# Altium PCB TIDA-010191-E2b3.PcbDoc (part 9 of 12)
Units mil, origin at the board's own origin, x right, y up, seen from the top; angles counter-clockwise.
Board outline 9842.52 x 9842.4 mil, 6 copper layers (Layer 1 - Top Layer, Layer 2 - GND Layer, Layer 3 - Signal, Layer 4 - Signal, Layer 5 - GND, Bottom Layer), stack 59.9 mil thick; 1178 components, 642 nets, 3329 pads, 2967 vias.
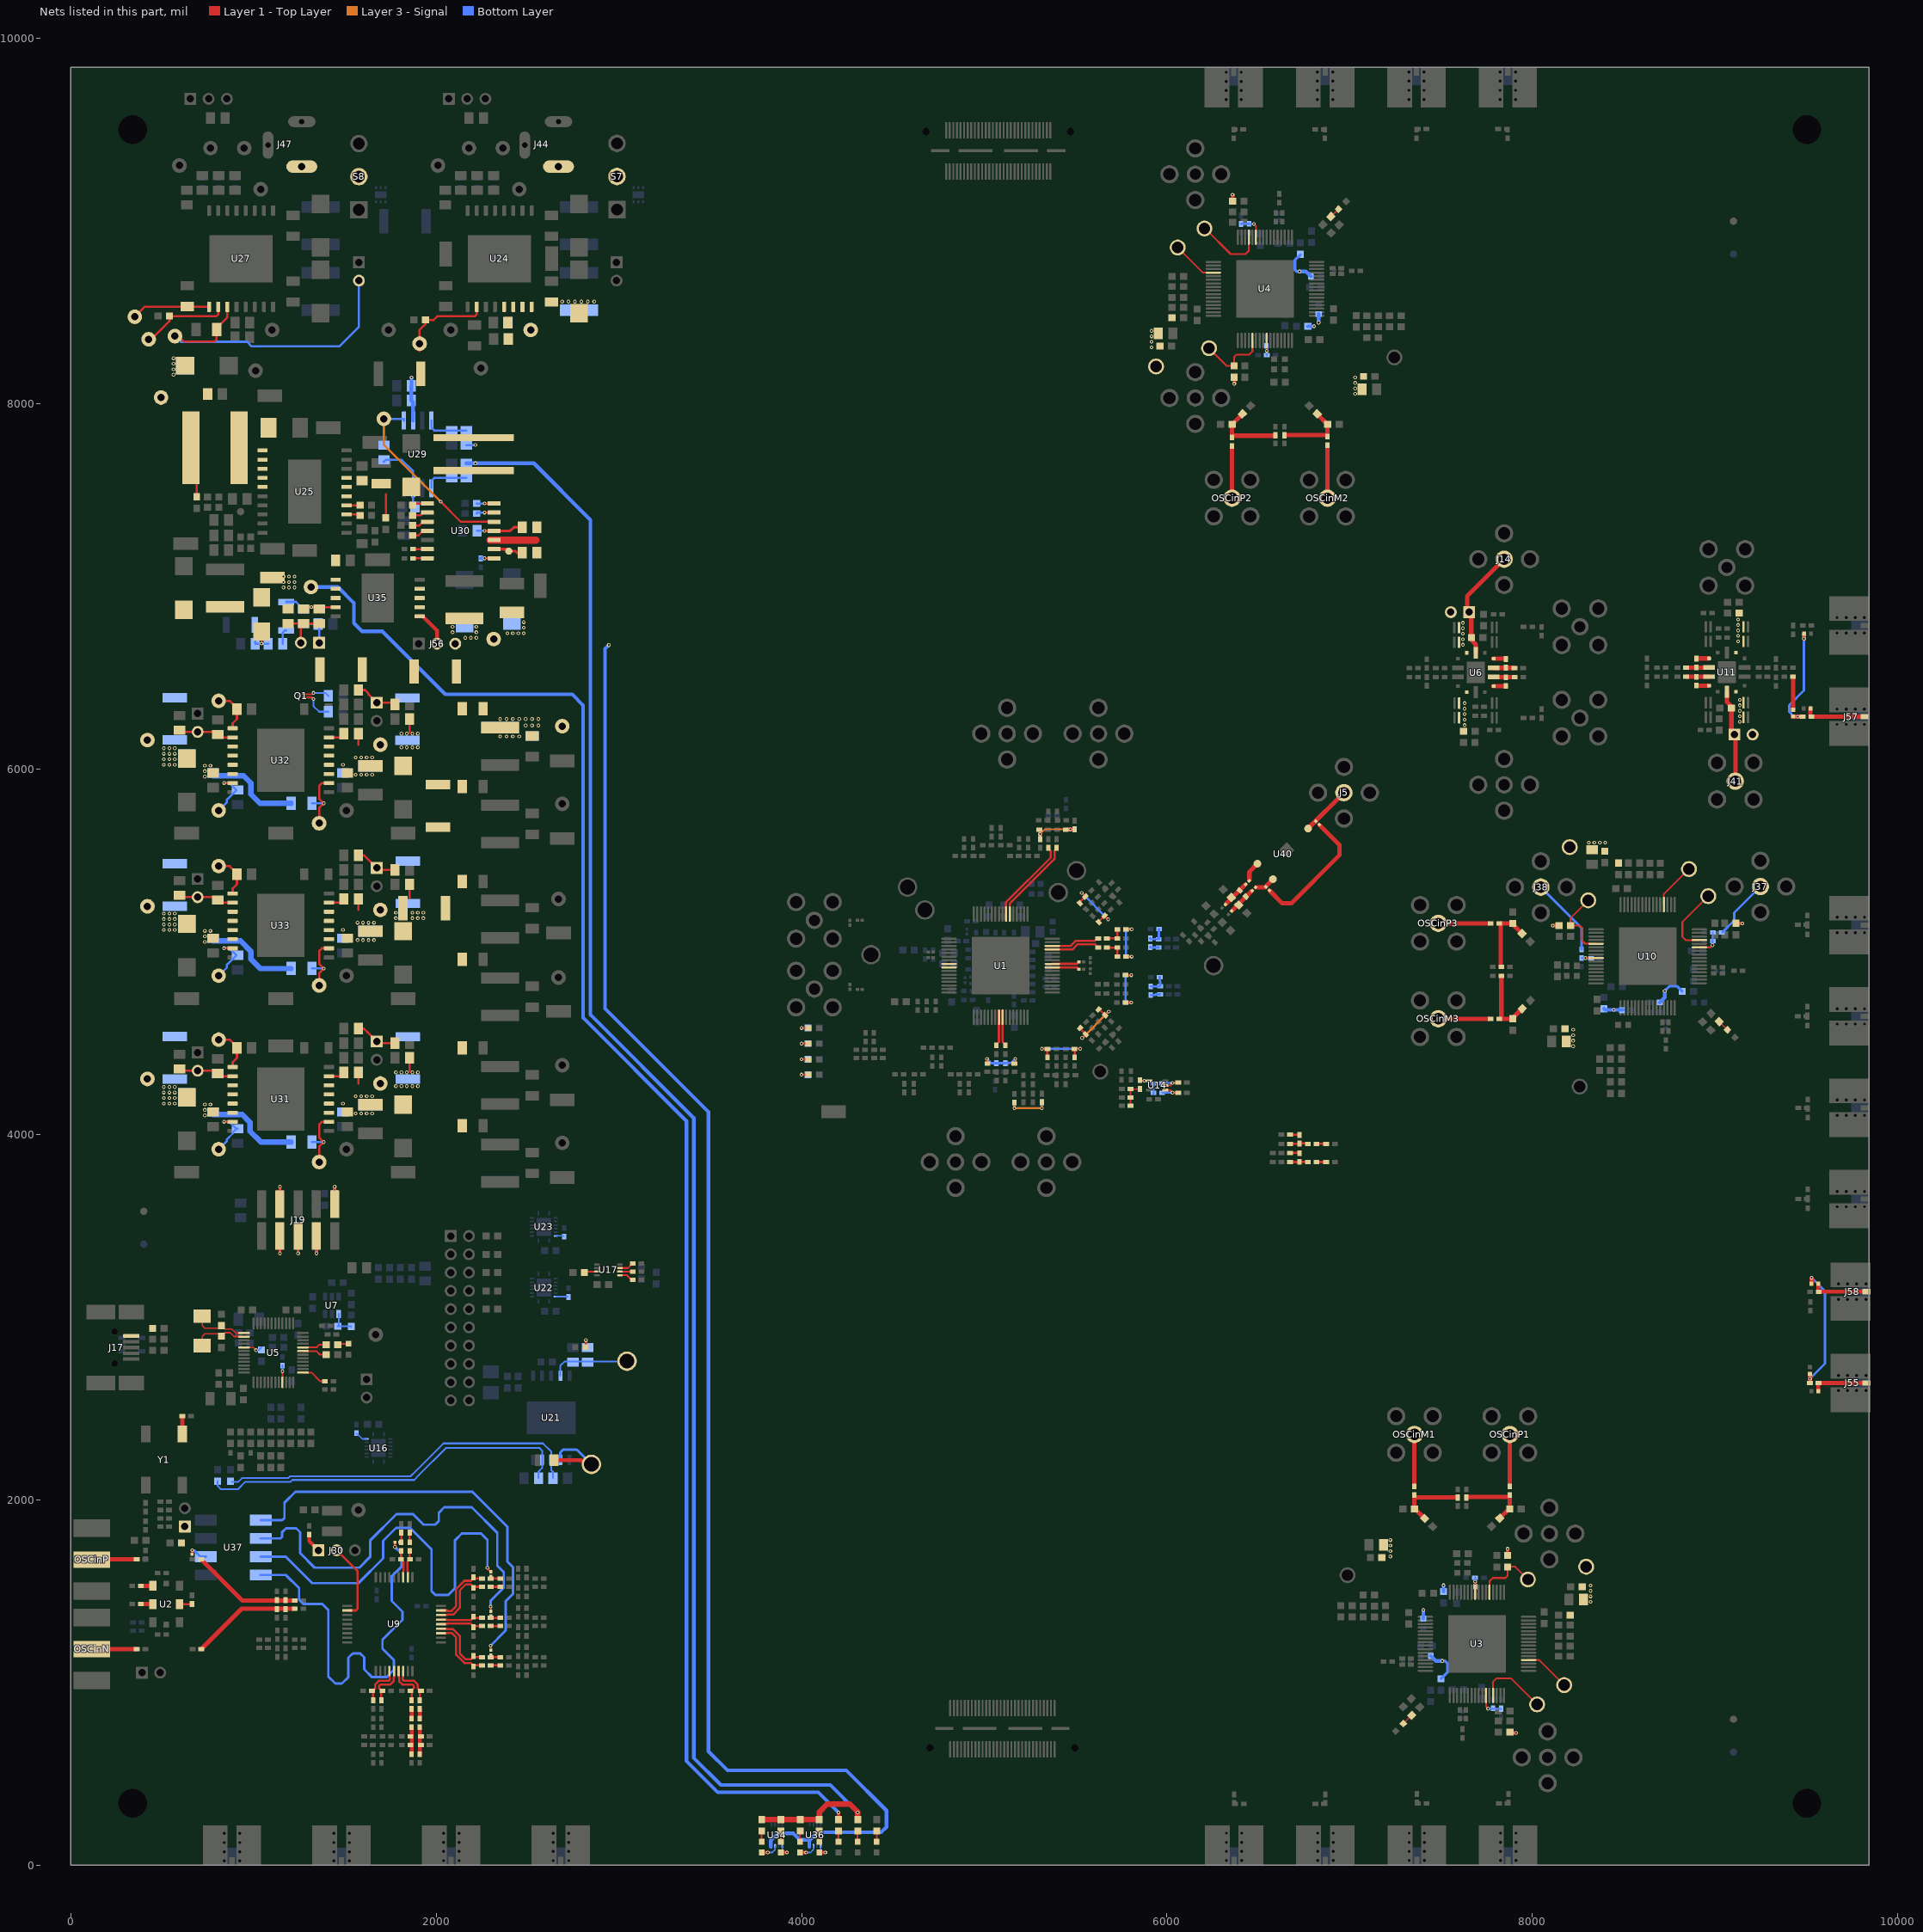
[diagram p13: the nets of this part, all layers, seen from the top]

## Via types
v1: diameter 20, hole 10, Layer 1 - Top Layer to Bottom Layer, tented both sides, 2595 vias
v2: diameter 19.68, hole 7.87, Layer 1 - Top Layer to Bottom Layer, 308 vias
v3: diameter 19.68, hole 7.87, Layer 1 - Top Layer to Bottom Layer, tented both sides, 25 vias
v4: diameter 20, hole 10, Layer 1 - Top Layer to Bottom Layer, 21 vias
v5: diameter 41, hole 25, Layer 1 - Top Layer to Bottom Layer, 10 vias
v6: diameter 24, hole 12, Layer 1 - Top Layer to Bottom Layer, tented both sides, 4 vias
v7: diameter 24, hole 8, Layer 1 - Top Layer to Bottom Layer, tented both sides, 1 vias
v8: diameter 24/24/24/24/24/24 (per signal layer), hole 8, Layer 1 - Top Layer to Bottom Layer, tented both sides, 1 vias
v9: diameter 30, hole 12, Layer 1 - Top Layer to Bottom Layer, tented both sides, 1 vias
v10: diameter 20/20/20/20/20/20 (per signal layer), hole 10, Layer 1 - Top Layer to Bottom Layer, tented both sides, 1 vias

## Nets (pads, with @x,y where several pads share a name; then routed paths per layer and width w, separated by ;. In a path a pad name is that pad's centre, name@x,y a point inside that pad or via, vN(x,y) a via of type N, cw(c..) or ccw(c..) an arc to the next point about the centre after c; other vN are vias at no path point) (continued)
NetC262_2: C262.2 J46.2 TP33.1 U27.11 | length 1736.6
  Layer 1 - Top Layer w12: TP33.1@562.99,8365.23 595.17,8365.23 620.08,8340.32 784.32,8340.32 799.02,8355.02 799.02,8405.93 C262.2@800.09,8407 800.09,8417.83 819.68,8437.42 820.57,8437.42 857.56,8474.41 U27.11@857.56,8531.5
  Bottom Layer w12: 602,8340 966,8340 991,8315 1470,8315 1577.56,8422.56 J46.2@1577.56,8675
NetC263_2: C263.2 TP31.1 U27.9 | length 430.3
  Layer 1 - Top Layer w12: TP31.1@351,8477 406.91,8532.91 C263.2@637.56,8532.91 638.97,8531.5 U27.9@757.56,8531.5
NetC264_1: C264.1 R485.1 U29.3 | length 391.1
  Bottom Layer w12: C264.1@1714.09,7683.58 1725.51,7695 1810,7695 1874.09,7630.91 U29.3@1874.09,7538.54 1874.09,7444.37 R485.1@1883.46,7435
NetC264_2: C264.2 TP37.1 U29.5 U30.5 | length 1184.5
  Layer 1 - Top Layer w12: v1(2025,7465) 2135,7355 U30.5@2318.07,7355
  Layer 3 - Signal w12: TP37.1@1714.09,7918.58 1714.09,7775.91 v1(2025,7465)
  Bottom Layer w12: C264.2@1714.09,7775 TP37.1@1714.09,7918.58 1824.09,7918.58 U29.5@1824.09,7908.62
NetC271_1: C271.1 U31.15 | length 89.8
  Layer 1 - Top Layer w12: U31.15@1413.5,4320 1475,4320 C271.1@1495,4340
NetC284_1: C284.1 TP47.1 U31.1 | length 236.6
  Layer 1 - Top Layer w12: TP47.1@810,4520 870.47,4520 910,4480.47 C284.1@910,4475 910,4420.47 886.5,4396.97 U31.1@886.5,4370
NetC290_1: C290.1 U32.15 | length 89.8
  Layer 1 - Top Layer w12: U32.15@1413.5,6174.53 1475,6174.53 C290.1@1495,6194.53
NetC303_1: C303.1 TP60.1 U32.1 | length 236.6
  Layer 1 - Top Layer w12: TP60.1@810,6374.53 870.47,6374.53 910,6335 C303.1@910,6329.53 910,6275 886.5,6251.5 U32.1@886.5,6224.53
NetC309_1: C309.1 U33.15 | length 89.8
  Layer 1 - Top Layer w12: U33.15@1413.5,5270 1475,5270 C309.1@1495,5290
NetC316_1: C316.1 R429.1 R433.1 R437.2 | length 147.8
  Layer 1 - Top Layer w22: R433.1@1866,608.62 C316.1@1866,756.38
NetC316_2: C316.2 R432.2 | length 52.8
  Layer 1 - Top Layer w22: C316.2@1866,803.62 R432.2@1866,856.38
NetC317_1: C317.1 R428.1 R431.1 R436.2 | length 147.8
  Layer 1 - Top Layer w22: R431.1@1911,608.62 1911,705 C317.1@1911,756.38
NetC317_2: C317.2 R430.2 | length 52.8
  Layer 1 - Top Layer w22: C317.2@1911,803.62 R430.2@1911,856.38
NetC318_2: C318.2 R210.1 R440.2 | length 52.8
  Layer 1 - Top Layer w12: R440.2@1810,1768.62 C318.2@1810,1821.38
NetC319_2: C319.2 R442.2 | length 52.8
  Layer 1 - Top Layer w12: R442.2@1855,1768.62 C319.2@1855,1821.38
NetC320_2: C320.2 R361.1 R450.2 | length 52.8
  Layer 1 - Top Layer w12: R450.2@2298.62,1570 C320.2@2351.38,1570
NetC321_2: C321.2 R452.2 | length 52.8
  Layer 1 - Top Layer w12: R452.2@2298.62,1525 C321.2@2351.38,1525
NetC322_2: C322.2 R363.1 R460.2 | length 52.8
  Layer 1 - Top Layer w12: R460.2@2298.62,1355 C322.2@2351.38,1355
NetC323_2: C323.2 R462.2 | length 52.8
  Layer 1 - Top Layer w12: R462.2@2298.62,1310 C323.2@2351.38,1310
NetC324_2: C324.2 R470.2 | length 52.8
  Layer 1 - Top Layer w12: R470.2@2298.62,1095 C324.2@2351.38,1095
NetC325_2: C325.2 R364.1 R472.2 | length 52.8
  Layer 1 - Top Layer w12: R472.2@2298.62,1140 C325.2@2351.38,1140
NetC331_1: C331.1 J55.1 L40.2 | length 306.7
  Layer 1 - Top Layer w22: L40.2@9564.87,2596.05 9564.87,2640.09 C331.1@9565.28,2640.49 9565.68,2640.9 9566.21,2640.9 9566.59,2640.52 J55.1@9827.09,2640.52
NetC331_2: C331.2 L14.2 L38.1 | length 698.3
  Layer 1 - Top Layer w22: C331.2@9518.04,2640.49 9518.09,2640.49 9519.07,2641.48 v1(9519.07,2663.67) L14.2@9519.07,2690 ; L38.1@9527.47,3185 v1(9527.47,3216.33)
  Bottom Layer w13.5: v1(9519.07,2663.67) 9601,2745.6 9601,3142.8 v1(9527.47,3216.33)
NetC332_1: C332.1 J57.1 L37.2 | length 342.3
  Layer 1 - Top Layer w22: C332.1@9521.32,6288.91 9522.13,6288.09 C332.1@9526.06,6288.09 C332.1@9526.27,6287.89
  Layer 1 - Top Layer w24: C332.1@9521.32,6288.91 L37.2@9521.32,6333 ; C332.1@9526.27,6287.89 J57.1@9819.06,6287.89
NetC332_2: C332.2 L32.2 L39.1 | length 573
  Layer 1 - Top Layer w22: L32.2@9426,6288.3 L32.2@9426.1,6288.2 ; C332.2@9478.72,6288.2 C332.2@9478.82,6288.09
  Layer 1 - Top Layer w24: L32.2@9426.1,6288.2 v1(9452.41,6288.2) C332.2@9478.72,6288.2 ; v1(9486.09,6715) L39.1@9486.09,6742.98
  Bottom Layer w13.5: v1(9452.41,6288.2) 9431.8,6288.2 9405,6315 9405,6350 9486.09,6431.09 v1(9486.09,6715)
NetC333_1: C333.1 J58.1 L38.2 | length 306.7
  Layer 1 - Top Layer w22: L38.2@9564.87,3185 9564.87,3140.96 9565.68,3140.15 C333.1@9566.21,3140.15 9566.59,3140.52 J58.1@9827.09,3140.52
NetC343_1: C343.1 TP73.1 U33.1 | length 236.6
  Layer 1 - Top Layer w12: TP73.1@810,5470 870.47,5470 910,5430.47 C343.1@910,5425 910,5370.47 886.5,5346.97 U33.1@886.5,5320
NetC345_2: C345.2 D22.2 R549.2 R551.2 | length 239.5
  Layer 1 - Top Layer w12: v1(1045,6687.56) C345.2@1045,6754.06
  Bottom Layer w12: D22.2@1008.74,6790 1010,6788.74 R551.2@1010,6687.56 v1(1045,6687.56) R549.2@1080,6687.56
NetC347_1: C347.1 J59.2 R547.1 R548.2 | length 281.2
  Layer 1 - Top Layer w12: R547.1@1190,6797.56 C347.1@1360,6797.56 ; J59.2@1260,6692.56 1260,6782.56 R548.2@1275,6797.56
NetC347_2: C347.2 D21.2 R548.1 R550.2 U35.9 | length 336.9
  Layer 1 - Top Layer w12: R548.1@1275,6877.56 1285,6887.56 v1(1317.48,6887.56) U35.9@1450.08,6887.56
  Bottom Layer w12: D21.2@1180,6916.3 1233.7,6916.3 1272.44,6877.56 R550.2@1275,6877.56 1279.48,6877.56 1289.48,6887.56 v1(1317.48,6887.56)
NetCE_TP1_1: CE_TP1.1 R90.2 U3.5 | length 399.5
  Layer 1 - Top Layer w10: U3.5@7765.16,1495.43 7765.16,1555.79 7782.35,1572.98 7852.35,1572.98 7864.34,1584.97 7864.34,1634.78 7905.55,1634.78 CE_TP1.1@8002.35,1537.98
NetCE_TP2_1: CE_TP2.1 R274.2 U4.5 | length 399.5
  Layer 1 - Top Layer w10: CE_TP2.1@6230,8305 6326.8,8208.2 R274.2@6368.01,8208.2 6368.01,8258.01 6380,8270 6450,8270 6467.19,8287.19 U4.5@6467.19,8347.55
NetCE_TP3_1: CE_TP3.1 R250.2 U10.5 | length 399.5
  Layer 1 - Top Layer w10: CE_TP3.1@8305.5,5282.55 8208.7,5185.75 R250.2@8208.7,5144.53 8258.51,5144.53 8270.5,5132.55 8270.5,5062.55 8287.69,5045.35 U10.5@8348.05,5045.35
NetD1_1: D1.1 R77.2 | length 72.8
  Layer 1 - Top Layer w10: v1(4000,4412) D1.1@4037.36,4412
  Bottom Layer w10: v1(4000,4412) R77.2@4035.39,4412
NetD2_1: D2.1 R78.2 | length 72.8
  Layer 1 - Top Layer w10: v1(4000,4328.46) D2.1@4037.36,4328.46
  Bottom Layer w10: v1(4000,4328.46) R78.2@4035.39,4328.46
NetD3_1: D3.1 R79.2 | length 72.8
  Layer 1 - Top Layer w10: v1(4000,4583.46) D3.1@4037.36,4583.46
  Bottom Layer w10: v1(4000,4583.46) R79.2@4035.39,4583.46
NetD4_1: D4.1 R80.2 | length 72.8
  Layer 1 - Top Layer w10: v1(4000,4498.46) D4.1@4037.36,4498.46
  Bottom Layer w10: v1(4000,4498.46) R80.2@4035.39,4498.46
NetD5_1: D5.1 R105.1 | length 58.6
  Layer 1 - Top Layer w8: D5.1@7293.64,776.51 7334.77,817.63 R105.1@7335.17,817.63
NetD6_1: D6.1 R314.1 | length 58.6
  Layer 1 - Top Layer w8: R314.1@6897.18,9025.35 6897.59,9025.35 D6.1@6938.71,9066.47
NetD7_2: D7.2 R388.2 | length 81.9
  Layer 1 - Top Layer w10: D7.2@2819.53,2837.44 v1(2819.53,2875)
  Bottom Layer w10: v1(2819.53,2875) 2819.53,2845.47 R388.2@2830,2835
NetD10_1: D10.1 R217.1 | length 60.4
  Layer 1 - Top Layer w10: R217.1@1461.5,2850.59 1466.02,2855.12 D10.1@1520,2855.12
NetD12_1: D12.1 L23.1 U25.11 U25.12 U25.13 U25.14 U25.15
NetD13_1: D13.1 R294.1 | length 58.6
  Layer 1 - Top Layer w8: R294.1@9025.85,4615.37 9025.85,4614.96 D13.1@9066.97,4573.84
NetD14_1: D14.1 R538.2 | length 59.2
  Layer 1 - Top Layer w10: D14.1@3781.28,129.65 3781.28,187.6 R538.2@3782.19,188.5
NetD14_2: D14.2 U34.7 | length 99.4
  Layer 1 - Top Layer w20: D14.2@3781.28,70.59 v1(3815,70.59)
  Bottom Layer w8: v1@3815.18,70.77 3839.49,70.77 3854.98,86.26 U34.7@3854.98,105.77
NetD15_1: D15.1 R539.2 | length 59.2
  Layer 1 - Top Layer w10: D15.1@3886.28,129.65 3886.28,187.6 R539.2@3887.19,188.5
NetD15_2: D15.2 U34.5 | length 89.5
  Layer 1 - Top Layer w20: D15.2@3886.28,70.59 v1(3920,70.59)
  Bottom Layer w8: U34.5@3894.53,105.94 3894.53,79.2 3903.14,70.59 v1(3920,70.59)
NetD16_1: D16.1 R540.2 | length 59.2
  Layer 1 - Top Layer w10: D16.1@3991.28,129.65 3991.28,187.6 R540.2@3992.19,188.5
NetD16_2: D16.2 U36.7 | length 99.9
  Layer 1 - Top Layer w20: D16.2@3991.28,70.59 v1(4025,70.59)
  Bottom Layer w8: v1(4025,70.59) 4049.31,70.59 4064.8,86.09 4064.8,105.59 U36.7@4065.16,105.94
NetD17_1: D17.1 R541.2 | length 59.2
  Layer 1 - Top Layer w10: D17.1@4096.28,129.65 4096.28,187.6 R541.2@4097.19,188.5
NetD17_2: D17.2 U36.5 | length 89.5
  Layer 1 - Top Layer w20: D17.2@4096.28,70.59 v1(4130,70.59)
  Bottom Layer w8: U36.5@4104.53,105.94 4104.53,79.2 4113.14,70.59 v1(4130,70.59)
NetD18_1: D18.1 R542.1 | length 59.2
  Layer 1 - Top Layer w10: D18.1@4201.28,129.65 4201.28,187.6 R542.1@4202.19,188.5
NetD19_1: D19.1 R543.1 | length 59.2
  Layer 1 - Top Layer w10: D19.1@4306.28,129.65 4306.28,187.6 R543.1@4307.19,188.5
NetD20_1: D20.1 R544.1 | length 59.2
  Layer 1 - Top Layer w10: D20.1@4411.28,129.65 4411.28,187.6 R544.1@4412.19,188.5
NetD21_1: D21.1 R549.1 | length 84.4
  Bottom Layer w12: R549.1@1160,6687.56 1160,6747.1 1171.72,6758.82 D21.1@1180,6758.82
NetJ5_1: J5.1 R106.1 U40.1 | length 277.4
  Layer 1 - Top Layer w24: U40.1@6772.06,5675.6 J5.1@6968.23,5871.77
NetJ8_1: J8.1 L13.2
NetJ12_1: J12.1 J14.1 R138.2 U6.9 | length 617.1
  Layer 1 - Top Layer w24: U6.9@7690,6637.28 7690,6683.41 7665,6708.41 7665,6848.15 J12.1@7653.25,6859.9 7641.49,6871.65 7642.72,6872.87 7642.72,6947.72 J14.1@7845,7150
NetJ17_1: J17.1 R383.1
NetJ19_1: J19.1 R306.2 | length 133.4
  Layer 1 - Top Layer w13.5: J19.1@1445,3620.06 v1(1445,3715)
  Bottom Layer w13.5: R306.2@1445,3676.5 v1(1445,3715)
NetJ19_4: J19.4 R303.2 | length 135.9
  Layer 1 - Top Layer w13.5: v1(1345,3350.12) J19.4@1345,3445.06
  Bottom Layer w13.5: v1(1345,3350.12) R303.2@1345,3391.06
NetJ19_6: J19.6 R304.2 | length 135.9
  Layer 1 - Top Layer w13.5: v1(1245,3350.12) J19.6@1245,3445.06
  Bottom Layer w13.5: v1(1245,3350.12) R304.2@1245,3391.06
NetJ19_7: J19.7 R307.2 | length 135.4
  Layer 1 - Top Layer w13.5: J19.7@1145,3620.06 v1(1145,3715)
  Bottom Layer w13.5: R307.2@1145,3674.55 v1(1145,3715)
NetJ19_8: J19.8 R302.2 | length 135.9
  Layer 1 - Top Layer w13.5: v1(1145,3350.12) J19.8@1145,3445.06
  Bottom Layer w13.5: v1(1145,3350.12) R302.2@1145,3391.06
NetJ30_1: J30.1 R175.1 | length 107.5
  Layer 1 - Top Layer w20: R175.1@1305,1811.38 1305.24,1811.14 1305.24,1775.76 J30.1@1356,1725
NetJ30_2: J30.2 U9.2 | length 421.9
  Layer 1 - Top Layer w12: J30.2@1461,1720 1571,1610 1571,1405 1561.48,1395.48 U9.2@1513.58,1395.48
NetJ37_1: J37.1 R271.2 | length 336.1
  Bottom Layer w13.5: R271.2@9039.73,5108.02 9103.55,5171.84 9103.55,5214.39 J37.1@9247.27,5358.11
NetJ38_1: J38.1 R278.2 | length 433.9
  Bottom Layer w13.5: J38.1@8045.58,5354.94 8269.61,5130.91 R278.2@8269.61,5013.86
NetJ40_1: J40.1 J41.1 R378.2 U11.9 | length 510.6
  Layer 1 - Top Layer w22: J41.1@9110,5935 J41.1@9111.22,5936.22
  Layer 1 - Top Layer w24: U11.9@9063.94,6424.46 9063.94,6369.06 9088.94,6344.06 R378.2@9088.94,6335.09 9088.94,6213.6 9112.44,6190.09 9111.22,6188.87 J41.1@9111.22,5936.22
NetJ44_1: J44.1 S7.2
NetJ47_1: J47.1 S8.2
NetJ49_1: J49.1 R511.1 R513.2 | length 233.1
  Layer 1 - Top Layer w12: R511.1@1575,4580 1605,4580 1625,4560 J49.1@1675,4510 1685,4500 R513.2@1775,4500
NetJ50_2: J50.2 R508.2 R510.2 U31.2 | length 308.1
  Layer 1 - Top Layer w12: R510.2@595,4360 605,4350 J50.2@695,4350 790,4350 R508.2@805,4335 820,4320 U31.2@886.5,4320
NetJ51_1: J51.1 R522.1 R524.2 | length 239.7
  Layer 1 - Top Layer w12: R522.1@1575,6434 1610.53,6434 1630,6414.53 1630,6409.53 J51.1@1675,6364.53 1771.5,6364.53 1775,6361.03 R524.2@1775,6354.53
NetJ52_2: J52.2 R519.2 R521.2 U32.2 | length 308.1
  Layer 1 - Top Layer w12: R521.2@595,6214.53 605,6204.53 J52.2@695,6204.53 790,6204.53 R519.2@805,6189.53 820,6174.53 U32.2@886.5,6174.53
NetJ53_1: J53.1 R535.1 R537.2 | length 233.1
  Layer 1 - Top Layer w12: R535.1@1575,5530 1605,5530 J53.1@1675,5460 1685,5450 R537.2@1775,5450
NetJ54_2: J54.2 R532.2 R534.2 U33.2 | length 308.1
  Layer 1 - Top Layer w12: R534.2@595,5310 605,5300 J54.2@695,5300 790,5300 R532.2@805,5285 820,5270 U33.2@886.5,5270
NetJ56_2: J56.2 U35.1 | length 199.6
  Layer 1 - Top Layer w20: U35.1@1909.92,6837.56 1927.44,6837.56 2005,6760 J56.2@2005,6687.56
NetJ59_1: J59.1 R550.1 R552.2 | length 185.6
  Bottom Layer w12: R550.1@1275,6797.56 1352.44,6797.56 R552.2@1355,6795 1360,6790 J59.1@1360,6692.56
NetL28_1: L28.1 L29.1 R525.1 R528.2
NetL32_1: L32.1 R374.2 | length 179
  Layer 1 - Top Layer w24: L32.1@9426.06,6327.7 R374.2@9426.06,6506.75
NetOSCinM3_1: OSCinM3.1 R316.2 | length 278.5
  Layer 1 - Top Layer w24: OSCinM3.1@7484.87,4634.05 R316.2@7763.37,4634.05
NetOSCinN_1: OSCinN.1 R37.1 | length 246.3
  Layer 1 - Top Layer w24: OSCinN.1@115.09,1183.92 R37.1@361.38,1183.92
NetOSCinP3_1: OSCinP3.1 R280.2 | length 278.5
  Layer 1 - Top Layer w24: OSCinP3.1@7484.87,5156.75 R280.2@7763.37,5156.75
NetOSCinP_1: OSCinP.1 R39.1 | length 246.3
  Layer 1 - Top Layer w24: OSCinP.1@115.09,1674.92 R39.1@361.38,1674.92
NetQ1_1: Q1.1 R385.2 | length 188
  Layer 1 - Top Layer w10: Q1.1@1276.53,6392.56 1320.61,6392.56 v1(1328.54,6384.63)
  Bottom Layer w10: v1(1328.54,6384.63) 1328.54,6346.46 1360,6315 R385.2@1410,6315
NetQ1_2: Q1.2 R384.2 | length 143.7
  Layer 1 - Top Layer w10: Q1.2@1276.53,6410.28 1320.61,6410.28 v1(1328.54,6418.21)
  Bottom Layer w10: v1(1328.54,6418.21) 1393.21,6418.21 R384.2@1410,6401.42
NetR11_1: R11.1 R12.1 R344.1 R345.2 | length 232.1
  Layer 1 - Top Layer w12: v1(5015,4415) 5015,4392.38 R12.1@5017.38,4390 R12.1@5020,4387.38 ; R11.1@5165,4389.62 R11.1@5164.62,4390 5170,4395.38 v1(5170,4415)
  Bottom Layer w12: v1(5015,4415) 5038.62,4391.38 R345.2@5115,4391.38 5115,4391.54 5146.54,4391.54 v1(5170,4415)
NetR13_1: R13.1 R14.1 R336.2 R337.2 | length 276.1
  Layer 1 - Top Layer w10: v1(5165,4145) R14.1@5165,4176.38 ; v1(5315.21,4145.32) R13.1@5315.21,4176.69
  Layer 3 - Signal w10: v1(5165,4145) 5165.16,4145.16 5314.84,4145.16 v1@5315,4145
  Bottom Layer w10: v1(5165,4145) R337.2@5165,4176.38 ; R336.2@5314.89,4176.38 R336.2@5315.21,4176.69 v1(5315.21,4145.32)
NetR21_1: R21.1 R22.1 R338.1 R339.1 | length 366.7
  Layer 1 - Top Layer w12: v1(5315,4470) R22.1@5346.38,4470 5345,4468.62 R339.1@5345,4423.62 ; R338.1@5495,4423.62 5495,4468.62 R21.1@5493.62,4470 v1(5525,4470)
  Bottom Layer w12: v1(5315,4470) v1(5525,4470)
NetR29_1: R29.1 R30.1 R290.1 R297.2 | length 279.2
  Layer 1 - Top Layer w12: R30.1@5773.51,4723.09 v1(5804.42,4723.09) ; R29.1@5773.51,4873.09 v1(5804.42,4873.09)
  Bottom Layer w12: v1(5804.42,4723.09) R297.2@5773.51,4723.09 5773.51,4869.16 5769.57,4873.09 R290.1@5773.51,4873.09 v1(5804.42,4873.09)
NetR31_1: R31.1 R32.1 R284.1 R285.2 | length 358.2
  Layer 1 - Top Layer w12: R32.1@5524.09,4583.3 5524.09,4579.91 R284.1@5555.3,4548.7 v1(5535.3,4528.7) ; R31.1@5625.31,4685.31 5629.69,4685.31 R285.2@5661.3,4653.7 v1(5681.3,4673.7)
  Layer 3 - Signal w12: v1@5535.8,4528.7 v1@5680.8,4673.7
NetR33_1: R33.1 Y1.1 | length 93.7
  Layer 1 - Top Layer w24: Y1.1@611.26,2361.3 R33.1@611.26,2455
NetR41_1: R41.1 R50.2 R288.1 | length 108.3
  Layer 1 - Top Layer w12: R288.1@5670,5024.09 R288.1@5670.51,5024.09 R41.1@5728.27,5024.09 R50.2@5728.27,4974.09
NetR42_1: R42.1 R49.2 R289.1 | length 108.3
  Layer 1 - Top Layer w12: R289.1@5670,5074.09 R289.1@5670.51,5074.09 R42.1@5728.27,5074.09 R49.2@5728.27,5124.09
NetR45_1: R45.1 U2.4@450.36,1530.27 | length 66.9
  Layer 1 - Top Layer w24: R45.1@383.62,1530 450.09,1530 U2.4@450.36,1530.27
NetR46_1: R46.1 U2.5@450.36,1430.27 | length 66.9
  Layer 1 - Top Layer w24: R46.1@383.62,1430 383.76,1430.14 450.22,1430.14 U2.5@450.36,1430.27
NetR47_1: R47.1 R48.1 R114.1 R291.2 | length 358.7
  Layer 1 - Top Layer w12: R47.1@5523.3,5266.7 5523.3,5273.3 R291.2@5553.3,5303.3 v1(5533.3,5323.3) ; R48.1@5626.7,5163.3 5626.7,5166.7 R114.1@5658.3,5198.3 v1(5678.3,5178.3)
  Bottom Layer w12: v1(5533.3,5323.3) v1(5678.3,5178.3)
NetR49_1: R49.1 R50.1 R115.1 R298.2 | length 279.2
  Layer 1 - Top Layer w12: R50.1@5775.51,4974.09 v1(5806.42,4974.09) ; R49.1@5775.51,5124.09 v1(5806.42,5124.09)
  Bottom Layer w12: v1(5806.42,4974.09) R298.2@5775.51,4974.09 5775.51,5120.16 5771.57,5124.09 R115.1@5775.51,5124.09 v1(5806.42,5124.09)
NetR51_2: R51.2 U2.2@596.03,1430.27 | length 68.2
  Layer 1 - Top Layer w12: U2.2@596.03,1430.27 663.87,1430.27 R51.2@664.09,1430.5
NetR58_1: R58.1 R59.1 R346.2 R366.1 | length 280.2
  Layer 1 - Top Layer w20: R58.1@5300.69,5670.69 R58.1@5301.38,5670 5305,5666.38 R346.2@5305,5617.62 ; R59.1@5446.62,5670 5447.31,5670.69 v1(5470.81,5670.69) 5494.31,5670.69 R366.1@5495,5671.38
  Layer 3 - Signal w10: v1(5305.15,5644.74) 5331.1,5670.69 v1(5470.81,5670.69)
NetR103_1: R103.1 R108.2 R111.2 R116.2 | length 149.2
  Layer 1 - Top Layer w24: R103.1@6357,5227 R111.2@6462.5,5332.5
NetR104_1: R104.1 R107.1 R238.1 R239.1 R240.1 | length 377.3
  Layer 1 - Top Layer w24: R238.1@7638.35,2016.87 R240.1@7875.6,2016.87 ; R107.1@7821.02,1900.28 R104.1@7874.1,1953.36 ; R104.1@7875.86,1951.61 R240.1@7875.86,2016.61
NetR106_2: R106.2 R164.1 | length 724.9
  Layer 1 - Top Layer w24: R164.1@6562.55,5334.91 6630.21,5267.25 6680.94,5267.25 6943.28,5529.59 6943.28,5586.18 R106.2@6836.55,5692.91
NetR111_1: R111.1 R164.2 U40.2 | length 108
  Layer 1 - Top Layer w24: R111.1@6490,5354.19 6535.5,5354.19 U40.2@6579.72,5398.41
NetR112_2: R112.2 R113.2 R242.1 R243.1 R244.1 | length 372.1
  Layer 1 - Top Layer w24: R244.1@7353.85,2013.56 7353.85,1954.91 R112.2@7409.48,1899.28 ; R244.1@7353.85,2013.62 R242.1@7588.6,2013.62
NetR116_1: R116.1 R117.2 R118.1 R120.1 | length 149.2
  Layer 1 - Top Layer w24: R120.1@6322,5262 R117.2@6427.5,5367.5
NetR117_1: R117.1 U40.3 | length 108
  Layer 1 - Top Layer w24: R117.1@6450.65,5393.54 6450.65,5439.04 U40.3@6494.87,5483.26
NetR122_1: R122.1 R124.2 U6.5 | length 115.2
  Layer 1 - Top Layer w24: U6.5@7787.44,6505 R124.2@7902.68,6505
NetR122_2: R122.2 U6.4 | length 68.8
  Layer 1 - Top Layer w24: U6.4@7787.44,6455 7854.81,6455 7855,6455.19 R122.2@7855,6456.38
NetR125_2: R125.2 R128.1 U6.6 | length 113.9
  Layer 1 - Top Layer w24: U6.6@7787.44,6555 R125.2@7901.38,6555
NetR128_2: R128.2 U6.7 | length 68.8
  Layer 1 - Top Layer w24: U6.7@7787.44,6605 7854.81,6605 7855,6604.81 R128.2@7855,6603.62
NetR142_1: R142.1 R166.1 R169.2 | length 103.1
  Bottom Layer w12: R169.2@5911.27,4811.54 5961.27,4811.54 R166.1@5962.65,4812.92
  Bottom Layer w13.5: R142.1@5959.89,4862.92 5959.89,4840.11 5962.65,4837.35 R166.1@5962.65,4812.92
NetR144_1: R144.1 R167.2 | length 52.8
  Layer 1 - Top Layer w12: R167.2@6818.62,3950 R144.1@6871.38,3950
NetR146_2: R146.2 R168.2 | length 51.9
  Layer 1 - Top Layer w12: R146.2@6673.62,3900 6723.62,3900 R168.2@6725,3898.62
NetR147_1: R147.1 U5.31 | length 135.3
  Layer 1 - Top Layer w10: U5.31@1271.42,2815.43 1344.57,2815.43 1364.41,2795.59 R147.1@1398.5,2795.59
NetR148_1: R148.1 R394.2 | length 52.8
  Layer 1 - Top Layer w12: R394.2@6818.62,3850 R148.1@6871.38,3850
NetR153_1: R153.1 U5.5 | length 109.5
  Layer 1 - Top Layer w8: U5.5@948.58,2835.12 999.88,2835.12 v1(1015,2820)
  Bottom Layer w8: v1(1015,2820) 1028.5,2820 R153.1@1045,2836.5
NetR160_1: R160.1 R163.2 U7.1 | length 144.3
  Bottom Layer w10: U7.1@1467.4,3018.35 1467.4,2956.5 R163.2@1461.5,2950.59 1533.5,2950.59 R160.1@1535,2949.09
NetR165_2: R165.2 R168.1 R394.1 | length 96.9
  Layer 1 - Top Layer w12: R165.2@6673.62,3850 R168.1@6723.62,3850 ; R168.1@6725,3851.38 6770,3851.38 R394.1@6771.38,3850
NetR167_1: R167.1 R392.1 R393.2 | length 98.9
  Layer 1 - Top Layer w12: R393.2@6673.62,3950 6723.62,3950 R392.1@6725,3951.38 6770,3951.38 R167.1@6771.38,3950
NetR169_1: R169.1 R203.1 | length 52.9
  Bottom Layer w12: R169.1@5911.27,4764.3 5934.3,4764.3 5937.92,4767.92 R203.1@5962.65,4767.92
NetR191_1: R191.1 R193.1 R195.1 U14.4 | length 165.5
  Layer 1 - Top Layer w10: R193.1@5851.89,4297.72 5854.92,4294.68 U14.4@5902.6,4294.68
  Bottom Layer w10: v1(5875,4295) 5876.91,4293.09 5909.35,4293.09 5922.44,4280 R195.1@5926.38,4280 R191.1@5926.38,4230 R191.1@5926.38,4225 ; R191.1@5923.27,4224.09 R191.1@5923.27,4225
NetR191_2: R191.2 R192.2 U14.1 | length 132.2
  Layer 1 - Top Layer w10: U14.1@5991.18,4243.5 6016.5,4243.5 v1(6030,4230) R192.2@6061.38,4230
  Bottom Layer w10: R191.2@5973.62,4230 v1(6030,4230)
NetR193_2: R193.2 R196.2 R197.1 R201.1 | length 141.9
  Layer 1 - Top Layer w8.6: R196.2@5800.51,4159.09 R197.1@5800.51,4204.09 R201.1@5800.51,4249.09 5850.51,4249.09 R193.2@5851.89,4250.47
NetR194_2: R194.2 R195.2 U14.2 | length 133.2
  Layer 1 - Top Layer w10: U14.2@5991.18,4269.09 6016.5,4269.09 v1(6030,4282.6) R194.2@6061.38,4282.6
  Bottom Layer w10: R195.2@5973.62,4280 5976.22,4282.6 v1(6030,4282.6)
NetR207_1: R207.1 U17.7 | length 68.5
  Layer 1 - Top Layer w10: R207.1@2812.92,3246.5 2816.59,3250.16 U17.7@2879.93,3250.16
NetR208_1: R208.1 R215.2 R216.1 | length 105.8
  Bottom Layer w13.5: R215.2@5907.17,5075.08 R215.2@5908.54,5073.7 5912.17,5070.08 R208.1@5954.92,5070.08 5954.92,5122.83 R216.1@5957.17,5125.08
NetR210_2: R210.2 U37.8 | length 2294.1
  Layer 1 - Top Layer w12: v1@1775.02,1743.1 R210.2@1775.02,1768
  Bottom Layer w13.5: U37.8@1040,1590 1176.96,1590 1249.8,1517.16 1249.8,1455.1 1274.9,1430 1377.8,1430 1410,1397.8 1410,1033.36 1448.36,995 1485,995 1520,1030 1520,1136.38 1544.59,1160.96 1584.04,1160.96 1606.38,1138.62 1606.38,1073.62 1650,1030 1728.62,1030 1768.91,1070.29 1768.91,1124.09 1706.7,1186.3 1706.7,1234.88 1816.06,1344.24 1816.06,1388.33 1757.68,1446.71 1757.68,1582.48 1810,1634.8 1810,1707.85 v1(1775.02,1742.83)
NetR213_1: R213.1 R245.1 R246.1 U3.43 | length 147.8
  Layer 1 - Top Layer w10: U3.43@7745.47,930.47 7745.47,869.86 v1(7757.35,857.98)
  Bottom Layer w10: v1(7757.35,857.98) 7782.35,857.98 7783.22,857.12 R246.1@7827.35,857.12
NetR214_1: R214.1 R247.1 R249.1 U3.9 | length 108
  Layer 1 - Top Layer w10: U3.9@7686.42,1495.43 v1(7686.42,1552.98)
  Bottom Layer w10: R214.1@7686.42,1525.54 v1(7686.42,1552.98) 7686.42,1574.51 R249.1@7686.93,1575.03 R249.1@7687.45,1575.54
NetR215_1: R215.1 R233.1 | length 46.9
  Bottom Layer w13.5: R215.1@5908.54,5026.46 5909.92,5025.08 R233.1@5954.92,5025.08
NetR217_2: R217.2 U5.32 | length 133.5
  Layer 1 - Top Layer w10: U5.32@1271.42,2835.12 1345.12,2835.12 1360.59,2850.59 R217.2@1398.5,2850.59
NetR218_1: R218.1 U17.2 | length 70.5
  Layer 1 - Top Layer w10: U17.2@3005.92,3250.16 3076.22,3250.16 R218.1@3076.38,3250
NetR219_1: R219.1 U17.1 | length 81
  Layer 1 - Top Layer w10: U17.1@3005.92,3230.47 3044.53,3230.47 3070,3205 R219.1@3076.38,3205
NetR267_1: R267.1 R273.1 R278.1 U10.9 | length 108
  Layer 1 - Top Layer w10: v1(8290.5,4966.61) U10.9@8348.05,4966.61
  Bottom Layer w10: R278.1@8267.94,4967.64 8268.97,4966.61 R278.1@8269.61,4966.61 v1(8290.5,4966.61) R267.1@8317.94,4966.61
NetR268_1: R268.1 R269.1 R271.1 U10.43 | length 147.8
  Layer 1 - Top Layer w10: U10.43@8913.01,5025.67 8973.62,5025.67 v1(8985.5,5037.55)
  Bottom Layer w10: v1(8985.5,5037.55) 8985.5,5062.55 8986.36,5063.41 R271.1@8986.36,5107.5
NetR272_1: R272.1 R277.1 R280.1 R281.1 R295.1 | length 377.3
  Layer 1 - Top Layer w24: R295.1@7826.61,4918.55 R280.1@7826.61,5155.8 ; R280.1@7826.87,5156.05 R277.1@7891.87,5156.05 ; R277.1@7890.12,5154.3 R281.1@7943.2,5101.22
NetR282_2: R282.2 U1.57 | length 196.7
  Layer 1 - Top Layer w12: U1.57@5099.84,4679 5099.84,4507.72 5115,4492.56 R282.2@5115,4488.62
NetR283_2: R283.2 U1.56 | length 196.6
  Layer 1 - Top Layer w12: R283.2@5065,4488.62 5065,4492.56 5080.11,4507.67 U1.56@5080.11,4679
NetR288_2: R288.2 U1.13 | length 303.9
  Layer 1 - Top Layer w12: U1.13@5336,5013.58 5481.49,5013.58 5509.3,5041.39 5606.15,5041.39 5618.45,5029.09 R288.2@5623.27,5029.09
NetR289_2: R289.2 U1.14 | length 304.2
  Layer 1 - Top Layer w12: U1.14@5336,5033.31 5473.31,5033.31 5501.39,5061.39 5605.15,5061.39 5617.85,5074.09 R289.2@5623.27,5074.09
NetR292_2: R292.2 U1.22 | length 505.6
  Layer 1 - Top Layer w12: U1.22@5139.26,5171 5139.26,5264.26 5384,5509 5384,5553 5396.3,5565.3 R292.2@5396.3,5570.12
NetR293_2: R293.2 U1.23 | length 505.6
  Layer 1 - Top Layer w12: U1.23@5119.53,5171 5119.53,5272.81 5364,5517.28 5364,5552 5351.3,5564.7 R293.2@5351.3,5570.12
NetR301_1: R301.1 R316.1 R317.2 R318.2 R319.1 | length 372.1
  Layer 1 - Top Layer w24: R316.1@7829.86,4634.05 R301.1@7829.86,4868.8 ; R316.1@7829.92,4634.05 7888.57,4634.05 7890.22,4635.7 R317.2@7944.2,4689.68
NetR323_1: R323.1 R324.2 U11.5 | length 125.9
  Layer 1 - Top Layer w24: R324.2@8840.64,6556.75 U11.5@8966.5,6556.75
NetR323_2: R323.2 U11.4 | length 70
  Layer 1 - Top Layer w22: R323.2@8897.02,6605.37 R323.2@8898.4,6606.75
  Layer 1 - Top Layer w24: R323.2@8898.4,6606.75 U11.4@8966.5,6606.75
NetR325_1: R325.1 R331.1 R332.1 R333.1 R348.1 | length 377.3
  Layer 1 - Top Layer w24: R332.1@6356.49,7826.37 R348.1@6356.49,7891.37 ; R332.1@6356.75,7826.12 R325.1@6594,7826.12 ; R348.1@6358.25,7889.62 R333.1@6411.33,7942.7
NetR326_2: R326.2 R328.1 U11.6 | length 125.9
  Layer 1 - Top Layer w24: R326.2@8840.64,6506.75 U11.6@8966.5,6506.75
NetR328_2: R328.2 U11.7 | length 70
  Layer 1 - Top Layer w22: R328.2@8897.02,6458.13 R328.2@8898.4,6456.75
  Layer 1 - Top Layer w24: R328.2@8898.4,6456.75 U11.7@8966.5,6456.75
NetR334_1: R334.1 R355.1 R358.1 U4.43 | length 147.8
  Layer 1 - Top Layer w10: v1(6475,8985) 6486.88,8973.12 U4.43@6486.88,8912.51
  Bottom Layer w10: R355.1@6405,8985.87 6449.13,8985.87 6450,8985 v1(6475,8985)
NetR340_2: R340.2 U5.21 | length 92.4
  Layer 1 - Top Layer w10: U5.21@1159.21,2644.17 v1(1159.21,2705)
  Bottom Layer w10: v1(1159.21,2705) 1159.61,2705.39 1159.61,2735.84 R340.2@1160,2736.23
NetR341_2: R341.2 U5.25 | length 139.3
  Layer 1 - Top Layer w10: U5.25@1271.42,2697.32 1317.68,2697.32 1364.41,2650.59 R341.2@1391.38,2650.59
NetR342_1: R342.1 R359.1 R360.1 U4.9 | length 108
  Layer 1 - Top Layer w10: v1(6545.93,8290) U4.9@6545.93,8347.55
  Bottom Layer w10: R360.1@6544.91,8267.44 6545.93,8268.47 v1(6545.93,8290) R342.1@6545.93,8317.44
NetR350_1: R350.1 R351.2 R352.1 R353.1 R354.2 | length 372.1
  Layer 1 - Top Layer w24: R350.1@6643.75,7829.37 6878.5,7829.37 6878.5,7888.07 R354.2@6822.87,7943.7
NetR361_2: R361.2 U37.7 | length 2259
  Layer 1 - Top Layer w13.5: v1(2280.62,1628.71) 2281.87,1627.47 2281.87,1624.91 2299,1607.78 R361.2@2299,1606.99
  Bottom Layer w13.5: U37.7@1040,1690 1177.5,1690 1322.5,1545 1575,1545 1710,1680 1710,1776.38 1781.12,1847.5 1857.12,1847.5 1975,1729.62 1975,1501.05 1996.05,1480 2066.38,1480 2102.37,1515.99 2102.37,1778.12 2141.56,1817.3 2245.18,1817.3 2280.62,1781.86 v1(2280.62,1628.71)
NetR362_2: R362.2 U37.2 | length 111.5
  Layer 1 - Top Layer w13.5: R362.2@665,1702.99 v1(665,1725)
  Bottom Layer w13.5: v1(665,1725) 666.24,1723.76 676.13,1723.76 709.88,1690 U37.2@740,1690
NetR363_2: R363.2 U37.6 | length 2282.3
  Layer 1 - Top Layer w12: R363.2@2299,1390.99 v1@2299,1415.89
  Bottom Layer w13.5: U37.6@1040,1790 1147.99,1790 1157.99,1800 1157.99,1824.92 1178.39,1845.31 1234.37,1845.31 1255.59,1824.09 1255.59,1709.41 1335,1630 1580,1630 1638.7,1688.7 1638.7,1777.58 1783.62,1922.5 1873.88,1922.5 1931.38,1865 1995,1865 2015,1885 2015,1930 2045,1960 2195,1960 2335,1820 2335,1640 2370,1605 2370,1519.62 2299,1448.62 v1(2299,1416.16)
NetR364_2: R364.2 U37.5 | length 2280.1
  Layer 1 - Top Layer w12: R364.2@2298.62,1177.99 v1@2298.62,1202.89
  Bottom Layer w13.5: U37.5@1040,1890 1131,1890 1131.3,1890 1157.99,1890 1170,1902.01 1170,1985 1230,2045 2198.51,2045 2390,1853.51 2390,1662.5 2420,1632.5 2420,1485 2380,1445 2380,1284.54 v1(2298.62,1203.16)
NetR371_2: R371.2 U16.15 | length 68.2
  Bottom Layer w8: R371.2@1563.62,2362.56 1567.44,2362.56 1595.79,2334.21 U16.15@1620.04,2334.21
NetR381_1: R381.1 U17.3 | length 80.9
  Layer 1 - Top Layer w10: U17.3@3005.92,3269.84 3049.84,3269.84 3075,3295 R381.1@3076.38,3295
NetR386_1: R386.1 TP9.1 U21.7 | length 466
  Layer 1 - Top Layer w20: R386.1@2645,2215 R386.1@2645,2217.44 2795.13,2217.44 2801.06,2211.51 2833.49,2211.51 TP9.1@2850,2195
  Bottom Layer w13.5: U21.7@2680,2220.08 2680,2260 2695,2275 2770,2275 TP9.1@2850,2195
NetR387_1: R387.1 R388.1 TP10.1 U21.4 | length 429.4
  Bottom Layer w10: U21.4@2680,2679.92 2680,2735 2702.44,2757.44 TP10.1@3045,2757.44
NetR389_2: R389.2 U22.15 | length 65
  Bottom Layer w8: U22.15@2654.96,3113.35 R389.2@2720,3113.35
NetR390_2: R390.2 U23.15 | length 46.9
  Bottom Layer w8: U23.15@2654.96,3445.79 2695.59,3445.79 R390.2@2700,3441.38
NetR391_2: R391.2 R392.2 | length 51.9
  Layer 1 - Top Layer w12: R391.2@6673.62,4000 6723.62,4000 R392.2@6725,3998.62
NetR397_1: R397.1 R401.2 U9.14 | length 239
  Layer 1 - Top Layer w12: R397.1@1700,903.62 1700,949.19 R401.2@1705.81,955 ; R401.2@1706.38,955 R401.2@1705.81,955 ; U9.14@1770.08,1063.98 1770.08,1029.89 1767.58,1027.39 1767.58,1008.29 1749.28,990 1695,990 1687,982 1687,971 1703,955 R401.2@1705.81,955
NetR399_1: R399.1 R402.2 U9.13 | length 238.6
  Layer 1 - Top Layer w12: R402.2@1648.62,955 R402.2@1649.19,955 ; R399.1@1655,903.62 1655,949.19 R402.2@1649.19,955 ; U9.13@1745.08,1063.98 1745.08,1029.92 1747.58,1027.42 1747.58,1016.58 1741,1010 1686.72,1010 1667,990.28 1667,970 1652,955 R402.2@1649.19,955
NetR412_1: R412.1 U25.4 | length 73.6
  Layer 1 - Top Layer w12: U25.4@1509.92,7445 R412.1@1583.5,7445
NetR414_1: R414.1 U25.3 | length 75.7
  Layer 1 - Top Layer w12: U25.3@1509.92,7395 1578.5,7395 R414.1@1583.5,7390
NetR419_2: R419.2 TP20.1 U24.10 | length 517.7
  Layer 1 - Top Layer w12: 1910,8290 TP20.1@1910,8330 1910,8405 1941.5,8436.5 R419.2@1941.5,8460 1986.56,8460 2006.56,8480 2211.91,8480 2222.56,8490.65 U24.10@2222.56,8531.5
NetR430_1: R430.1 R434.2 U9.16 | length 239.4
  Layer 1 - Top Layer w12: U9.16@1820.08,1063.98 1820.08,1029.92 1817.58,1027.42 1817.58,1016.58 1824.15,1010 1879.28,1010 1899,990.28 1899,970 1914,955 R434.2@1916.81,955 ; R430.1@1911,903.62 1911,949.19 R434.2@1916.81,955 ; R434.2@1917.38,955 R434.2@1916.81,955
NetR432_1: R432.1 R435.2 U9.15 | length 239.8
  Layer 1 - Top Layer w12: U9.15@1795.08,1063.98 1795.08,1029.89 1797.58,1027.39 1797.58,1008.29 1815.87,990 1871,990 1879,982 1879,971 1863,955 R435.2@1860.19,955 ; R435.2@1859.62,955 R435.2@1860.19,955 ; R432.1@1866,903.62 1866,949.19 R435.2@1860.19,955
NetR440_1: R440.1 R444.2 U9.30 | length 152.6
  Layer 1 - Top Layer w12: R440.1@1810,1721.38 1810,1677.38 R444.2@1807.62,1675 1822.58,1660.05 1822.58,1613.58 1820.08,1611.08 U9.30@1820.08,1576.98
NetR442_1: R442.1 R445.2 U9.29 | length 152.5
  Layer 1 - Top Layer w12: U9.29@1845.08,1576.98 1845.08,1611.04 1842.58,1613.54 1842.58,1660.2 R445.2@1857.38,1675 1855,1677.38 R442.1@1855,1721.38
NetR450_1: R450.1 R454.2 U9.26 | length 362.2
  Layer 1 - Top Layer w12: U9.26@2026.58,1395.48 2060.67,1395.48 2063.17,1392.98 2084.7,1392.98 2110,1418.28 2110,1513.28 2154.7,1557.98 2190.54,1557.98 2199.19,1566.63 2205,1572.44 R454.2@2205,1575.81 ; R454.2@2205,1576.38 R454.2@2205,1575.81 ; R450.1@2251.38,1570 2210.81,1570 R454.2@2205,1575.81
NetR452_1: R452.1 R455.2 U9.25 | length 362.6
  Layer 1 - Top Layer w12: U9.25@2026.58,1370.48 2060.63,1370.48 2063.13,1372.98 2092.98,1372.98 2130,1410 2130,1505 2162.98,1537.98 2189.58,1537.98 2199.19,1528.37 2205,1522.56 R455.2@2205,1519.19 ; R455.2@2205,1518.62 R455.2@2205,1519.19 ; R452.1@2251.38,1525 2210.81,1525 R455.2@2205,1519.19
NetR460_1: R460.1 R464.2 U9.24 | length 238.2
  Layer 1 - Top Layer w12: U9.24@2026.58,1345.48 2060.67,1345.48 2063.17,1342.98 2190.54,1342.98 2199.19,1351.63 2205,1357.44 R464.2@2205,1360.81 ; R464.2@2205,1361.38 R464.2@2205,1360.81 ; R460.1@2251.38,1355 2210.81,1355 R464.2@2205,1360.81
NetR462_1: R462.1 R465.2 U9.23 | length 238.6
  Layer 1 - Top Layer w12: U9.23@2026.58,1320.48 2060.63,1320.48 2063.13,1322.98 2189.58,1322.98 2199.19,1313.37 2205,1307.56 R465.2@2205,1304.19 ; R465.2@2205,1303.62 R465.2@2205,1304.19 ; R462.1@2251.38,1310 2210.81,1310 R465.2@2205,1304.19
NetR470_1: R470.1 R474.2 U9.21 | length 362.2
  Layer 1 - Top Layer w12: U9.21@2026.58,1270.48 2060.67,1270.48 2063.17,1272.98 2084.7,1272.98 2110,1247.68 2110,1152.68 2154.7,1107.98 2190.54,1107.98 2199.19,1099.33 2205,1093.52 R474.2@2205,1090.15 ; R474.2@2205,1089.59 R474.2@2205,1090.15 ; R470.1@2251.38,1095.96 2210.81,1095.96 R474.2@2205,1090.15
NetR472_1: R472.1 R475.2 U9.22 | length 362.6
  Layer 1 - Top Layer w12: U9.22@2026.58,1295.48 2060.63,1295.48 2063.13,1292.98 2092.98,1292.98 2130,1255.96 2130,1160.96 2162.98,1127.98 2189.58,1127.98 2199.19,1137.59 2205,1143.4 R475.2@2205,1146.38 R475.2@2205,1146.78 ; R475.2@2205,1147.34 R475.2@2205,1146.78 ; R472.1@2251.38,1140.96 2210.81,1140.96 R475.2@2205,1146.78
NetR480_2: R480.2 TP34.1 U27.10 | length 481.2
  Layer 1 - Top Layer w12: TP34.1@442,8354 540.5,8452.5 R480.2@540.5,8481 542.33,8479.16 796.07,8479.16 807.56,8490.65 U27.10@807.56,8531.5
NetR486_2: R486.2 R491.2 U29.1 | length 235
  Bottom Layer w12: U29.1@1974.09,7541.38 1974.09,7578.78 1990.31,7595 R491.2@2085,7595 R486.2@2165,7595
NetR487_2: R487.2 R492.2 U30.4 | length 254.3
  Layer 1 - Top Layer w12: v1(2265,7305) U30.4@2318.07,7305
  Layer 1 - Top Layer w15: U30.4@2318.07,7305 2406,7305 2426,7325 R487.2@2471,7325
  Bottom Layer w12: R492.2@2225,7305 v1(2265,7305)
NetR488_2: R488.2 TP38.1 U30.2 | length 159
  Layer 1 - Top Layer w15: U30.2@2318.07,7205 2389.34,7205 TP38.1@2389.34,7194 ; TP38.1@2398,7194 2434,7194 2443,7185 R488.2@2471,7185
NetR489_2: R489.2 R490.2 U29.8 | length 235
  Bottom Layer w12: U29.8@1974.09,7908.62 1974.09,7871.22 1990.31,7855 R490.2@2085,7855 R489.2@2165,7855
NetR493_2: R493.2 U30.7 | length 96.6
  Layer 1 - Top Layer w12: v1(2265,7455) U30.7@2318.07,7455
  Bottom Layer w12: R493.2@2221.5,7455 v1(2265,7455)
NetR494_2: R494.2 U30.1 | length 73.6
  Layer 1 - Top Layer w12: v1(2265,7155) U30.1@2318.07,7155
  Bottom Layer w20: R494.2@2245,7153.62 2246.38,7155 v1(2265,7155)
NetR495_2: R495.2 U30.6 | length 98.6
  Layer 1 - Top Layer w12: v1(2265,7405) U30.6@2318.07,7405
  Bottom Layer w12: R495.2@2221.5,7400 2226.5,7405 v1(2265,7405)
NetR496_2: R496.2 U30.9 | length 86.6
  Layer 1 - Top Layer w12: R496.2@1871.5,7390 1915,7390 1930,7405 U30.9@1951.93,7405
NetR497_2: R497.2 U30.14 | length 78.3
  Layer 1 - Top Layer w12: R497.2@1873.62,7155 U30.14@1951.93,7155
NetR498_2: R498.2 U30.8 | length 84.6
  Layer 1 - Top Layer w12: R498.2@1871.5,7445 1881.5,7455 U30.8@1951.93,7455
NetR499_2: R499.2 U30.11 | length 90.8
  Layer 1 - Top Layer w12: R499.2@1871.5,7280 1903.31,7280 1928.31,7305 U30.11@1951.93,7305
NetR500_2: R500.2 U30.13 | length 78.3
  Layer 1 - Top Layer w12: R500.2@1873.62,7205 U30.13@1951.93,7205
NetR501_2: R501.2 U30.10 | length 88.7
  Layer 1 - Top Layer w12: R501.2@1871.5,7335 1908.31,7335 1928.31,7355 U30.10@1951.93,7355
NetR502_1: R502.1 R503.1
NetR504_1: R504.1 TP44.1 U31.10 | length 350.3
  Layer 1 - Top Layer w12: TP44.1@1360,3850 1360,3934.17 v1(1385,3959.17) 1360,3984.17 1360,4055.47 1375,4070.47 1413.03,4070.47 U31.10@1413.5,4070
  Bottom Layer w12: R504.1@1320.79,3959.17 v1(1385,3959.17)
NetR512_2: R512.2 TP45.1 U31.7 | length 337.9
  Layer 1 - Top Layer w10: 850,4070 U31.7@886.5,4070
  Layer 1 - Top Layer w12: v1(840,4070.47) 886.03,4070.47 U31.7@886.5,4070
  Bottom Layer w12: TP45.1@815,3915 TP45.1@810,3920 855,3965 855,3973.82 887.65,4006.47 887.65,4012.97 R512.2@906.65,4031.97 ; v1(840,4070.47) 840.47,4070 868.62,4070 R512.2@906.65,4031.97 ; R512.2@906.65,4031.97 R512.2@913.15,4031.97 R512.2@906.65,4031.97
NetR514_1: R514.1 R515.1
NetR516_1: R516.1 TP57.1 U32.10 | length 349.6
  Layer 1 - Top Layer w12: TP57.1@1360,5704.53 1360,5788.7 v1(1385,5813.7) 1360,5838.7 1360,5910 1375,5925 U32.10@1413.03,5925
  Bottom Layer w12: R516.1@1320.79,5813.7 v1(1385,5813.7)
NetR523_2: R523.2 TP58.1 U32.7 | length 287.7
  Layer 1 - Top Layer w12: v1(840,5925) 886.03,5925 U32.7@886.5,5924.53
  Bottom Layer w12: TP58.1@815,5769.53 TP58.1@810,5774.53 855,5819.53 855,5834.85 906.65,5886.5 868.62,5924.53 v1@840.47,5924.53
NetR526_1: R526.1 R527.1
NetR529_1: R529.1 TP70.1 U33.10 | length 350.3
  Layer 1 - Top Layer w12: TP70.1@1360,4800 TP70.1@1360,4817 1360,4884.17 v1(1385,4909.17) 1360,4934.17 1360,5005.47 1375,5020.47 1413.03,5020.47 U33.10@1413.5,5020
  Bottom Layer w12: R529.1@1320.79,4909.17 v1(1385,4909.17)
NetR536_2: R536.2 TP71.1 U33.7 | length 317.1
  Layer 1 - Top Layer w10: 850,5020 U33.7@886.5,5020
  Layer 1 - Top Layer w12: v1(840,5020.47) 886.03,5020.47 U33.7@886.5,5020
  Bottom Layer w12: TP71.1@810,4870 855,4915 855,4930.32 906.65,4981.97 868.62,5020 v1@840.47,5020
NetR545_1: R545.1 R546.1
NetR553_2: R553.2 U1.8 | length 148.7
  Layer 1 - Top Layer w12: U1.8@5372.48,4915.16 5506.85,4915.16 R553.2@5517.01,4905
NetR554_2: R554.2 U1.9 | length 148.7
  Layer 1 - Top Layer w12: U1.9@5372.48,4934.84 5506.85,4934.84 R554.2@5517.01,4945
NetR557_1: R557.1 R559.2 U21.9 | length 2067.1
  Bottom Layer w10: R559.2@804.71,2103.5 804.71,2076.95 822.27,2059.39 915.17,2059.39 955.77,2100 1203.48,2100 1213.48,2110 1880,2110 1905,2135 2055,2285 2565,2285 2580,2270 U21.9@2580,2220.08 2580,2175 2560,2155 R557.1@2560,2120
NetR558_1: R558.1 R560.2 U21.8 | length 2003.4
  Bottom Layer w10: R560.2@881.41,2100 917.46,2100 937.46,2120 1190.07,2120 1200.07,2130 1860,2130 1890,2160 2040,2310 2585,2310 2630,2265 U21.8@2630,2220.08 2630,2164.5 2640,2154.5 R558.1@2640,2120
NetRMPCLK1_1: RMPCLK1.1 U3.45 | length 381.7
  Layer 1 - Top Layer w9.84: U3.45@7784.84,930.47 7784.84,1005.47 7802.35,1022.98 7883.66,1022.98 RMPCLK1.1@8025.51,881.14
NetRMPCLK2_1: RMPCLK2.1 U4.45 | length 381.7
  Layer 1 - Top Layer w9.84: RMPCLK2.1@6206.84,8961.84 6348.69,8820 6430,8820 6447.51,8837.51 U4.45@6447.51,8912.51
NetRMPCLK3_1: RMPCLK3.1 U10.45 | length 381.7
  Layer 1 - Top Layer w9.84: U10.45@8913.01,5065.04 8838.01,5065.04 8820.5,5082.55 8820.5,5163.86 RMPCLK3.1@8962.34,5305.7
NetRMPDIR1_1: RMPDIR1.1 U3.52 | length 251.9
  Layer 1 - Top Layer w9.84: U3.52@7978.74,1124.37 8036.28,1124.37 RMPDIR1.1@8173.74,986.91
NetRMPDIR2_1: RMPDIR2.1 U4.52 | length 251.9
  Layer 1 - Top Layer w9.84: RMPDIR2.1@6058.61,8856.08 6196.08,8718.61 U4.52@6253.61,8718.61
NetRMPDIR3_1: RMPDIR3.1 U10.52 | length 251.9
  Layer 1 - Top Layer w9.84: U10.52@8719.11,5258.94 8719.11,5316.47 RMPDIR3.1@8856.58,5453.94
OSCI: C125.2 U5.1 Y2.1 | length 289.4
  Layer 1 - Top Layer w8: Y2.1@720,3006.3 720,2955 733.82,2941.18 C125.2@812.09,2941.18 ; C125.2@825,2954.09 843.41,2935.68 882.15,2935.68 903.98,2913.86 U5.1@948.58,2913.86
OSCin1_N: OSCinM1.1 R244.2 | length 278.5
  Layer 1 - Top Layer w24: R244.2@7353.85,2080.11 OSCinM1.1@7353.85,2358.61
OSCin1_P: OSCinP1.1 R240.2 | length 278.5
  Layer 1 - Top Layer w24: R240.2@7876.55,2080.11 OSCinP1.1@7876.55,2358.61
OSCin2_N: OSCinM2.1 R353.2 | length 278.5
  Layer 1 - Top Layer w24: OSCinM2.1@6878.5,7484.37 R353.2@6878.5,7762.88
OSCin2_P: OSCinP2.1 R332.2 | length 278.5
  Layer 1 - Top Layer w24: OSCinP2.1@6355.8,7484.37 R332.2@6355.8,7762.88
OSCIN+: C12.2 R38.1 R40.1 R198.2 | length 604.6
  Layer 1 - Top Layer w24: C12.2@714.98,1674.93 939.91,1450 R38.1@1226.38,1450
OSCIN-: C9.2 R34.1 R36.1 R199.2 | length 603
  Layer 1 - Top Layer w24: C9.2@714.98,1183.92 936.06,1405 R36.1@1226.38,1405
OSCO: C126.1 U5.2 Y2.2 | length 307.7
  Layer 1 - Top Layer w8: Y2.2@720,2844.88 720,2895 735,2910 812.09,2910 C126.1@825,2897.09 825,2898.07 839.7,2912.77 840.69,2912.77 843.91,2916 874,2916 895.83,2894.17 U5.2@948.58,2894.17
OSCout_N: U1.40
OSCout_P: U1.41
P3V3_LMX: C51.2 C52.2 C53.2 C54.2 C121.2 C122.2 C123.2 C127.2 C160.2 C161.2 C162.2 C163.2 C286.2 C287.2 C288.1 C289.1 L26.2 R83.1 R85.1 R87.1 R88.1 R89.2 R90.1 R91.2 R226.1 R227.1 R228.1 R231.1 R232.2 R250.1 R251.1 R253.2 R254.2 R255.1 R256.1 R257.1 R259.2 R274.1 TP54.1 Vcc_TP1.1 Vcc_TP2.1 Vcc_TP3.1 | length 1072.2
  Layer 1 - Top Layer w20: R254.2@6358.5,9110 v1(6358.5,9145) ; v1(6368.01,8110.21) R274.1@6368.01,8145.21 ; R90.1@7864.34,1697.77 v1(7864.34,1732.77) ; R89.2@7876.5,730 7881.5,725 v1(7910,725) ; v1(8110.71,5144.53) R250.1@8145.71,5144.53 ; R232.2@9113.48,5156.69 v1(9148.48,5156.69)
  Bottom Layer w15: v1(6725,8725) 6710,8725 6700,8735 6700,8787.52 6730,8817.52 R251.1@6730,8818.5 ; R87.1@7500,1021.5 7500,1022.48 7535,1057.48 7535,1105 7520.95,1119.05 v1(7506.78,1119.05) ; v1(8723.94,4786.97) 8748.96,4812 8791.52,4812 8818.52,4785 R226.1@8819.5,4785
  Bottom Layer w20: v1(6725,8725) 6760.77,8725 6787.35,8698.43 R255.1@6787.35,8697.44 ; R257.1@6771.5,8425 v1(6805,8425) ; v1(6830,8445) R256.1@6830,8492.44 ; R85.1@7402.35,1350.54 v1(7402.35,1397.98) ; R88.1@7444.43,1145.63 7471,1119.05 v1(7506.78,1119.05) ; R83.1@7512.98,1499.14 v1(7512.98,1532.65) ; R227.1@8391,4688.5 8396.96,4682.55 v1(8445.5,4682.55) R228.1@8492.94,4682.55 ; R231.1@8697.36,4724.63 8723.94,4751.2 v1(8723.94,4786.97)
  other v1: 8318.61,1442.44 8318.61,1472.44 8318.61,1502.44 8318.61,1532.44 7222.18,1690.62 7222.18,1720.62 7222.18,1750.62 7222.18,1780.62 8223.18,4484.38 8223.18,4514.38 8223.18,4544.38 8223.18,4574.38 8308.56,5598.61 8338.56,5598.61 8368.56,5598.61 8398.56,5598.61 2350,6180 2385,6180 2420,6180 2455,6180 2490,6240 2525,6240 2560,6240 2350,6275 2385,6275 2420,6275 2455,6275 2490,6275 2525,6275 2560,6275 7030,8055 7030,8085 7030,8115 7030,8145 5915,8310 5915,8340 5915,8370 5915,8400
P3V3A: C271.2 C274.1 C277.1 C278.1 C279.1 L24.1 L25.1 R503.2 R505.2 R507.1 TP39.1 U31.11 U31.12 U31.13 U31.14 | length 134.1
  Layer 1 - Top Layer w12: 1575,4280.47 C271.2@1575,4340 ; 1855,4345.47 R505.2@1855,4420
  other v1: 1560,4115.47 1590,4115.47 1620,4115.47 1650,4115.47 1490,4170.47 1560,4210.47 1590,4210.47 1620,4210.47 1650,4210.47 1780,4265.47 1810,4265.47 1840,4265.47 1870,4265.47 1900,4265.47 1780,4340.47 1810,4340.47 1840,4340.47 1870,4340.47 1900,4340.47
P3V3B: C290.2 C293.1 C296.1 C297.1 C298.1 L26.1 L27.1 R515.2 R517.2 R518.1 R525.2 TP52.1 U32.11 U32.12 U32.13 U32.14 | length 134.1
  Layer 1 - Top Layer w12: 1575,6135 C290.2@1575,6194.53 ; 1855,6200 R517.2@1855,6274.53
  other v1: 1560,5970 1590,5970 1620,5970 1650,5970 1490,6025 1560,6065 1590,6065 1620,6065 1650,6065 1810,6120 1840,6120 1870,6120 1900,6120 1810,6195 1840,6195 1870,6195 1900,6195
P3V3C: C309.2 C312.1 C315.1 C326.1 C334.1 R527.2 R528.1 R530.2 R531.1 TP65.1 U33.11 U33.12 U33.13 U33.14 | length 134.1
  Layer 1 - Top Layer w12: 1575,5230.47 C309.2@1575,5290 ; 1855,5295.47 R530.2@1855,5370
  other v1: 1570,5065 1600,5065 1630,5065 1660,5065 1490,5120.47 1570,5160 1600,5160 1630,5160 1660,5160 1780,5185 1870,5185 1900,5185 1930,5185 1780,5215.47 1870,5215.47 1900,5215.47 1930,5215
P3V8: C230.1 C231.1 C232.1 C272.1 C273.1 C275.1 C276.1 C291.1 C292.1 C294.1 C295.1 C310.1 C311.1 C313.1 C314.1 L23.2 R409.2 R502.2 R504.2 R506.2 R514.2 R516.2 R526.2 R529.2 TP13.1 TP40.1 TP53.1 TP66.1 U31.3 U31.4 U31.5 U31.6 U32.3 U32.4 U32.5 U32.6 U33.3 U33.4 U33.5 U33.6 | length 1837.6
  Layer 1 - Top Layer w12: L23.2@659.09,7760 690,7729.09 R409.2@690,7491.5
  Bottom Layer w30: C294.1@780,5965 947.03,5965 987.03,5925 987.03,5862.97 1036.3,5813.7 R516.2@1206.61,5813.7 ; C276.1@780.24,4110.24 938.65,4110.24 982.5,4066.39 982.5,4018.5 1041.83,3959.17 R504.2@1206.61,3959.17 ; C313.1@780.24,5060.24 929.92,5060.24 987.18,5002.98 987.18,4960.82 1038.83,4909.17 R529.2@1206.61,4909.17
  other v1: 735,4105.47 735,4135.47 735,4165.47 765,4165.47 510,4170.47 540,4170.47 570,4170.47 510,4200.47 540,4200.47 570,4200.47 510,4230.47 540,4230.47 570,4230.47 510,4260.47 540,4260.47 570,4260.47 735,5055.47 735,5085.47 735,5115.47 765,5115.47 510,5120.47 540,5120.47 570,5120.47 510,5150.47 540,5150.47 570,5150.47 510,5180.47 540,5180.47 570,5180.47 510,5210.47 540,5210.47 570,5210.47 735,5960 735,5990 735,6020 765,6020 510,6025 540,6025 570,6025 510,6055 540,6055 570,6055 510,6085 540,6085 570,6085 510,6115 540,6115 570,6115 563,8160 563,8190 563,8220 563,8250
P4V5: C41.1 C42.2 C43.1 C63.1 C197.1 C198.1 C200.2 C201.1 C345.1 C346.1 C348.1 C349.1 C350.1 J12.2 J40.2 R137.1 R377.1 R542.2 R546.2 R547.2 TP79.1 U6.1 U6.10 U11.1 U11.10 U35.6 U35.7 U35.8 | length 8822.3
  Layer 1 - Top Layer w20: R542.2@4202.19,251.5 v1(4202.19,290)
  Bottom Layer w20: TP79.1@1315,6997.56 1462.44,6997.56 1550,6910 1550,6800 1595,6755 1705,6755 2050,6410 2745,6410 2805,6350 2805,6289.68 2805,4640 3370,4075 3370,571.78 3541.78,400 4092.19,400 v1(4202.19,290)
  other v1: 7628.94,6241.75 9135,6260 7628.94,6271.75 9135,6290 7628.94,6301.75 9135,6320 7628.94,6331.75 9135,6350 7628.94,6361.75 9135,6380 7618.94,6681.75 9125,6700 7618.94,6711.75 9125,6730 7618.94,6741.75 9125,6760 7618.94,6771.75 9125,6790 7618.94,6801.75 9125,6820 1165,6995 1195,6995 1225,6995 1165,7025 1195,7025 1225,7025 1165,7055 1195,7055 1225,7055
P5V0: C224.1 C225.1 C237.1 C238.2 C240.1 C265.1 C266.1 C351.1 C352.1 C353.1 C354.1 J56.3 R407.1 R423.2 R487.1 R488.1 R489.1 R545.2 TP12.1 TP78.1 U24.13 U24.14 U24.15 U24.16 U29.6 U30.3 U34.8 U35.2 U35.3 U35.4 U36.8 | length 8805.2
  Layer 1 - Top Layer w40: U30.3@2295,7255 U30.3@2318.07,7255 2546,7255
  Bottom Layer w12: R489.1@2165,7775 v1(2215,7775)
  Bottom Layer w20: v1(1865,8145) 1865,8099.49 C265.1@1864.09,8098.58 C266.1@1864.09,8018.58 1874.09,8008.58 U29.6@1874.09,7908.62 ; v1(2945,6680) 2925,6660 2925,4690 3490,4125 3490,625 3595,520 4245,520 4465,300 4465,210 4436,181 4086.47,181 4045.47,140 ; U34.8@3832,102 3832,136.53 3870.47,175 3955,175 3990,140 4045.47,140 ; U36.8@4042,102 4042,136.53 4045.47,140
  other v1: 2160,6720 2190,6720 2220,6720 2390,6745 2420,6745 2450,6745 2480,6745 2090,6750 2220,6750 2480,6775 2090,6780 2220,6780 2480,6805 2690,8560 2725,8560 2760,8560 2795,8560 2830,8560 2865,8560
P5V0*: C233.1 C235.1 C236.1 R407.2 R411.2 R486.1 R538.1 R539.1 R540.1 R541.1 R543.2 U25.5 U25.6 U25.7 | length 9610.6
  Layer 1 - Top Layer w12: R411.2@1725,7376.5 1725,7505
  Layer 1 - Top Layer w30: R538.1@3782.19,251.5 R539.1@3887.19,251.5 R540.1@3992.19,251.5 R541.1@4097.19,251.5 4097.19,292.19 4140,335 4265,335 4307.19,292.81 v1(4307.19,290) R543.2@4307.19,251.5
  Bottom Layer w20: R486.1@2165,7675 v1(2215,7675) 2535,7675 2845,7365 2845,6303.91 2845,4656.57 3410,4091.57 3410,588.35 3558.35,440 4157.19,440 v1(4307.19,290)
